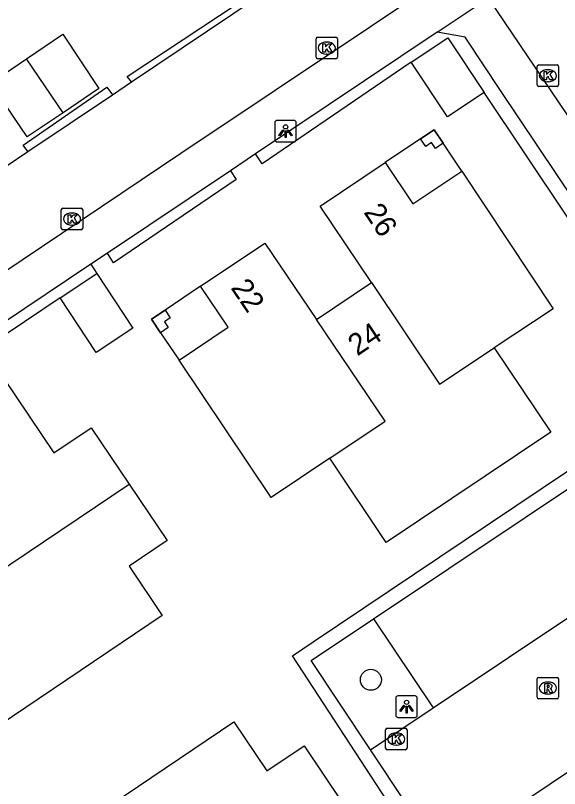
# Model space of a CAD drawing. Extents: x 158797 to 159887, y 384318 to 385255.
# Drawn here: x 158996.31 to 159021.65, y 384716.62 to 384752.65 of the extents above; entities that cross this region are included whole.
import ezdxf

# ---------------------------------------------------------------- set-up
doc = ezdxf.new("R2010")
doc.units = 0
for name, color, linetype in [('IMGEO_Boom', 7, 'Continuous'), ('IMGEO_Haag', 7, 'Continuous'), ('IMGEO_Kolk', 7, 'Continuous'), ('IMGEO_Lichtpunt', 7, 'Continuous'), ('IMGEO_Pand', 7, 'Continuous'), ('IMGEO_Pand_nummerreeks', 7, 'Continuous'), ('IMGEO_Pand_overbouw', 7, 'Continuous'), ('IMGEO_Parkeervlak_open', 7, 'Continuous'), ('IMGEO_Rijbaan_lokaal_open', 7, 'Continuous'), ('IMGEO_Rioolput', 7, 'Continuous'), ('IMGEO_Voetpad_open', 7, 'Continuous')]:
    doc.layers.add(name, color=color, linetype=linetype)

msp = doc.modelspace()

# ---------------------------------------------------------------- linework, layer by layer
at = {"layer": 'IMGEO_Boom'}
msp.add_circle((159012.861, 384721.691), 0.489, dxfattribs=at)
at = {"layer": 'IMGEO_Haag'}
for points in [[(159001.704, 384749.55), (159001.506, 384749.803), (159013.591, 384757.809), (159013.365, 384758.121)], [(159014.747, 384750.473), (159007.792, 384745.742), (159007.494, 384746.203)], [(158996.888, 384746.311), (158996.658, 384746.61), (159000.557, 384749.303), (159000.822, 384748.956)], [(159025.835, 384737.531), (159018.137, 384749.057)], [(159006.317, 384745.413), (159006.581, 384745.008), (159000.876, 384741.122), (159000.598, 384741.578)], [(158999.813, 384741.052), (159000.089, 384740.621)], [(158998.381, 384739.491), (158985.085, 384730.536)], [(159005.088, 384700.795), (159017.999, 384709.332), (159009.213, 384722.809), (159010.167, 384723.465), (159023.158, 384732.172), (159023.556, 384731.598)], [(159012.842, 384718.427), (159010.075, 384722.589), (159012.982, 384724.532)]]:
    msp.add_lwpolyline(points, dxfattribs=at)
at = {"layer": 'IMGEO_Kolk'}
for p, q in [((159010.383, 384751.632), (159011.235, 384751.632)), ((159010.308, 384750.706), (159010.308, 384751.558)), ((159010.796, 384751.412), (159010.821, 384751.412)), ((159011.309, 384751.558), (159011.309, 384750.706)), ((159011.235, 384750.632), (159010.383, 384750.632)), ((159010.819, 384750.852), (159010.794, 384750.852)), ((159020.607, 384749.417), (159020.607, 384750.269)), ((159020.682, 384750.343), (159021.534, 384750.343)), ((159021.608, 384750.269), (159021.608, 384749.417)), ((159021.095, 384750.123), (159021.12, 384750.123)), ((159021.118, 384749.563), (159021.093, 384749.563)), ((159021.534, 384749.343), (159020.682, 384749.343)), ((158998.441, 384742.738), (158998.441, 384743.59)), ((158998.516, 384743.664), (158999.368, 384743.664)), ((158998.929, 384743.444), (158998.954, 384743.444)), ((158999.442, 384743.59), (158999.442, 384742.738)), ((158999.368, 384742.664), (158998.516, 384742.664)), ((158998.952, 384742.884), (158998.927, 384742.884)), ((159013.547, 384718.503), (159013.547, 384719.355)), ((159013.622, 384719.429), (159014.474, 384719.429)), ((159014.035, 384719.209), (159014.06, 384719.209)), ((159014.548, 384719.355), (159014.548, 384718.503)), ((159014.058, 384718.649), (159014.033, 384718.649)), ((159014.474, 384718.429), (159013.622, 384718.429))]:
    msp.add_line(p, q, dxfattribs=at)
for points in [[(159010.383, 384751.632), (159011.235, 384751.632)], [(159010.308, 384750.706), (159010.308, 384751.558)], [(159010.629, 384751.332), (159010.752, 384751.332), (159010.752, 384751.181), (159010.882, 384751.332), (159011.046, 384751.332), (159010.9, 384751.181), (159011.053, 384750.932), (159010.901, 384750.932), (159010.816, 384751.096), (159010.752, 384751.029), (159010.752, 384750.932), (159010.629, 384750.932), (159010.629, 384751.332)], [(159011.309, 384751.558), (159011.309, 384750.706)], [(159011.235, 384750.632), (159010.383, 384750.632)], [(159020.607, 384749.417), (159020.607, 384750.269)], [(159020.682, 384750.343), (159021.534, 384750.343)], [(159021.608, 384750.269), (159021.608, 384749.417)], [(159020.928, 384750.043), (159021.051, 384750.043), (159021.051, 384749.892), (159021.181, 384750.043), (159021.345, 384750.043), (159021.199, 384749.892), (159021.352, 384749.643), (159021.2, 384749.643), (159021.115, 384749.807), (159021.051, 384749.74), (159021.051, 384749.643), (159020.928, 384749.643), (159020.928, 384750.043)], [(159021.534, 384749.343), (159020.682, 384749.343)], [(158998.441, 384742.738), (158998.441, 384743.59)], [(158998.516, 384743.664), (158999.368, 384743.664)], [(158998.762, 384743.364), (158998.885, 384743.364), (158998.885, 384743.213), (158999.015, 384743.364), (158999.179, 384743.364), (158999.033, 384743.213), (158999.186, 384742.964), (158999.034, 384742.964), (158998.949, 384743.128), (158998.885, 384743.061), (158998.885, 384742.964), (158998.762, 384742.964), (158998.762, 384743.364)], [(158999.442, 384743.59), (158999.442, 384742.738)], [(158999.368, 384742.664), (158998.516, 384742.664)], [(159013.547, 384718.503), (159013.547, 384719.355)], [(159013.622, 384719.429), (159014.474, 384719.429)], [(159014.548, 384719.355), (159014.548, 384718.503)], [(159013.868, 384719.129), (159013.991, 384719.129), (159013.991, 384718.978), (159014.121, 384719.129), (159014.285, 384719.129), (159014.139, 384718.978), (159014.292, 384718.729), (159014.14, 384718.729), (159014.055, 384718.893), (159013.991, 384718.826), (159013.991, 384718.729), (159013.868, 384718.729), (159013.868, 384719.129)], [(159014.474, 384718.429), (159013.622, 384718.429)]]:
    msp.add_lwpolyline(points, dxfattribs=at)
for centre, start, end in [((159010.385, 384751.556), 91.552, 178.448), ((159010.385, 384751.556), 91.552, 178.448), ((159011.233, 384751.556), 1.552, 88.448), ((159011.233, 384751.556), 1.552, 88.448), ((159010.385, 384750.708), 181.552, 268.448), ((159010.385, 384750.708), 181.552, 268.448), ((159011.233, 384750.708), 271.552, 358.448), ((159011.233, 384750.708), 271.552, 358.448), ((159020.684, 384750.267), 91.552, 178.448), ((159020.684, 384750.267), 91.552, 178.448), ((159021.532, 384750.267), 1.552, 88.448), ((159021.532, 384750.267), 1.552, 88.448), ((159020.684, 384749.419), 181.552, 268.448), ((159020.684, 384749.419), 181.552, 268.448), ((159021.532, 384749.419), 271.552, 358.448), ((159021.532, 384749.419), 271.552, 358.448), ((158998.518, 384743.588), 91.552, 178.448), ((158998.518, 384743.588), 91.552, 178.448), ((158999.366, 384743.588), 1.552, 88.448), ((158999.366, 384743.588), 1.552, 88.448), ((158998.518, 384742.74), 181.552, 268.448), ((158998.518, 384742.74), 181.552, 268.448), ((158999.366, 384742.74), 271.552, 358.448), ((158999.366, 384742.74), 271.552, 358.448), ((159013.624, 384719.353), 91.552, 178.448), ((159013.624, 384719.353), 91.552, 178.448), ((159014.472, 384719.353), 1.552, 88.448), ((159014.472, 384719.353), 1.552, 88.448), ((159013.624, 384718.505), 181.552, 268.448), ((159013.624, 384718.505), 181.552, 268.448), ((159014.472, 384718.505), 271.552, 358.448), ((159014.472, 384718.505), 271.552, 358.448)]:
    msp.add_arc(centre, 0.0765, start, end, dxfattribs=at)
for centre, major_axis, ratio, start_param, end_param in [((159010.795, 384751.132), (-0.387, 0.002), 0.722429, 4.712389, 7.853982), ((159010.82, 384751.132), (-0.39, 0.002), 0.717154, 1.570796, 4.712389), ((159021.094, 384749.843), (-0.387, 0.002), 0.722429, 4.712389, 7.853982), ((159021.119, 384749.843), (-0.39, 0.002), 0.717154, 1.570796, 4.712389), ((158998.928, 384743.164), (-0.387, 0.002), 0.722429, 4.712389, 7.853982), ((158998.953, 384743.164), (-0.39, 0.002), 0.717154, 1.570796, 4.712389), ((159014.034, 384718.929), (-0.387, 0.002), 0.722429, 4.712389, 7.853982), ((159014.059, 384718.929), (-0.39, 0.002), 0.717154, 1.570796, 4.712389)]:
    msp.add_ellipse(centre, major_axis=major_axis, ratio=ratio, start_param=start_param, end_param=end_param, dxfattribs=at)
at = {"layer": 'IMGEO_Lichtpunt'}
for p, q in [((159008.389, 384747.661), (159008.389, 384746.854)), ((159008.389, 384747.661), (159008.389, 384746.854)), ((159009.291, 384747.756), (159008.483, 384747.756)), ((159009.291, 384747.756), (159008.483, 384747.756)), ((159009.385, 384746.854), (159009.385, 384747.661)), ((159009.385, 384746.854), (159009.385, 384747.661)), ((159008.483, 384746.76), (159009.291, 384746.76)), ((159008.483, 384746.76), (159009.291, 384746.76)), ((159014.025, 384720.841), (159014.025, 384720.034)), ((159014.025, 384720.841), (159014.025, 384720.034)), ((159014.927, 384720.936), (159014.119, 384720.936)), ((159014.927, 384720.936), (159014.119, 384720.936)), ((159015.021, 384720.034), (159015.021, 384720.841)), ((159015.021, 384720.034), (159015.021, 384720.841)), ((159014.119, 384719.94), (159014.927, 384719.94)), ((159014.119, 384719.94), (159014.927, 384719.94))]:
    msp.add_line(p, q, dxfattribs=at)
for points in [[(159008.763, 384747.325), (159008.802, 384747.297), (159008.614, 384747.035), (159008.576, 384747.062), (159008.763, 384747.325)], [(159008.975, 384747.297), (159009.013, 384747.324), (159009.2, 384747.062), (159009.161, 384747.034), (159008.975, 384747.297)], [(159008.865, 384747.277), (159008.912, 384747.277), (159008.912, 384746.955), (159008.865, 384746.955), (159008.865, 384747.277)], [(159014.399, 384720.505), (159014.438, 384720.477), (159014.25, 384720.215), (159014.212, 384720.242), (159014.399, 384720.505)], [(159014.501, 384720.457), (159014.548, 384720.457), (159014.548, 384720.135), (159014.501, 384720.135), (159014.501, 384720.457)], [(159014.611, 384720.477), (159014.649, 384720.504), (159014.836, 384720.242), (159014.797, 384720.214), (159014.611, 384720.477)]]:
    msp.add_lwpolyline(points, dxfattribs=at)
for centre in [(159008.888, 384747.459), (159014.524, 384720.639)]:
    msp.add_circle(centre, 0.0994, dxfattribs=at)
for centre, start, end in [((159008.483, 384747.661), 90, 180), ((159008.483, 384747.661), 90, 180), ((159009.291, 384747.661), 0, 90), ((159009.291, 384747.661), 0, 90), ((159008.483, 384746.854), 180, 270), ((159008.483, 384746.854), 180, 270), ((159009.291, 384746.854), 270, 0), ((159009.291, 384746.854), 270, 360), ((159014.119, 384720.841), 90, 180), ((159014.119, 384720.841), 90, 180), ((159014.927, 384720.841), 0, 90), ((159014.927, 384720.841), 0, 90), ((159014.119, 384720.034), 180, 270), ((159014.119, 384720.034), 180, 270), ((159014.927, 384720.034), 270, 0), ((159014.927, 384720.034), 270, 360)]:
    msp.add_arc(centre, 0.0946, start, end, dxfattribs=at)
at = {"layer": 'IMGEO_Pand'}
for points in [[(158996.826, 384750.634), (158998.512, 384751.771), (159000.194, 384749.239), (158998.525, 384748.114)], [(159014.747, 384750.473), (159016.454, 384751.602), (159018.137, 384749.057)], [(158998.525, 384748.114), (158996.856, 384746.988), (158995.142, 384749.498), (158996.826, 384750.634)], [(158998.525, 384748.114), (158996.826, 384750.634)], [(159018.137, 384749.057), (159016.43, 384747.928), (159014.747, 384750.473)], [(159015.181, 384746.903), (159015.812, 384747.326), (159016.233, 384746.692), (159015.873, 384746.453), (159015.692, 384746.727), (159015.421, 384746.545), (159015.181, 384746.903)], [(159012.888, 384740.205), (159010.501, 384743.765), (159013.524, 384745.792), (159014.813, 384743.869), (159017.093, 384745.398), (159021.356, 384738.981), (159018.612, 384737.158)], [(159010.952, 384732.017), (159008.216, 384730.184), (159003.926, 384736.586), (159006.214, 384738.12), (159004.933, 384740.031), (159007.921, 384742.034), (159010.323, 384738.485)], [(159000.089, 384740.621), (159001.773, 384738.074), (159000.064, 384736.944), (158998.381, 384739.491)], [(158998.381, 384739.491), (159000.089, 384740.621)], [(159010.323, 384738.485), (159012.888, 384740.205)], [(159012.888, 384740.205), (159016.065, 384735.466), (159018.612, 384737.158)], [(159003.068, 384737.866), (159002.645, 384738.497), (159003.277, 384738.921), (159003.517, 384738.564), (159003.242, 384738.379), (159003.426, 384738.105), (159003.068, 384737.866)], [(159010.952, 384732.017), (159013.531, 384733.745), (159010.323, 384738.485)], [(159018.612, 384737.158), (159021.247, 384733.229), (159013.582, 384728.093), (159010.952, 384732.017)], [(158992.843, 384724.915), (158991.489, 384726.935), (158990.206, 384726.066), (158988.253, 384728.972), (158991.72, 384731.305), (158990.929, 384732.482), (158995.765, 384735.737), (158998.096, 384732.273), (158999.83, 384733.44), (159001.601, 384730.81)], [(159001.601, 384730.81), (159003.371, 384728.179), (159001.599, 384726.98), (159003.147, 384724.692), (158994.867, 384719.112), (158992.908, 384722.031), (158994.197, 384722.896), (158992.843, 384724.915)], [(158992.843, 384724.915), (159001.601, 384730.81)], [(159002.777, 384710.103), (159001.438, 384712.108), (159000.155, 384711.252), (158998.21, 384714.157), (159006.484, 384719.734), (159008.008, 384717.448), (159009.754, 384718.619), (159011.528, 384715.977)]]:
    msp.add_lwpolyline(points, dxfattribs=at)
at = {"layer": 'IMGEO_Pand_overbouw'}
for points in [[(159013.524, 384745.792), (159014.813, 384743.869), (159017.093, 384745.398), (159016.233, 384746.692), (159015.812, 384747.326), (159015.181, 384746.903)], [(159004.933, 384740.031), (159003.277, 384738.921), (159002.645, 384738.497), (159003.068, 384737.866), (159003.926, 384736.586), (159006.214, 384738.12)]]:
    msp.add_lwpolyline(points, close=True, dxfattribs=at)
at = {"layer": 'IMGEO_Parkeervlak_open'}
for points in [[(159012.982, 384724.532), (159023.556, 384731.598)], [(159012.982, 384724.532), (159015.764, 384720.383)]]:
    msp.add_lwpolyline(points, dxfattribs=at)
at = {"layer": 'IMGEO_Rijbaan_lokaal_open'}
for points in [[(159001.704, 384749.55), (159015.82, 384759.045), (159010.765, 384766.591)], [(159017.243, 384755.079), (159004.006, 384746.223), (158979.975, 384730.054), (158992.379, 384711.59), (159004.736, 384693.195)], [(159018.325, 384753.477), (159026.727, 384741.032), (159033.174, 384731.422)], [(159000.822, 384748.956), (159001.704, 384749.55)], [(158996.888, 384746.311), (159000.822, 384748.956)], [(158995.868, 384745.624), (158996.888, 384746.311)], [(159015.764, 384720.383), (159026.289, 384727.424)], [(159031.875, 384723.961), (159019.105, 384715.414)], [(159012.842, 384718.427), (159015.764, 384720.383)], [(159016.136, 384713.472), (159012.842, 384718.427)]]:
    msp.add_lwpolyline(points, dxfattribs=at)
at = {"layer": 'IMGEO_Rioolput'}
for p, q in [((159020.609, 384720.878), (159020.609, 384721.73)), ((159020.684, 384721.804), (159021.536, 384721.804)), ((159021.61, 384721.73), (159021.61, 384720.878)), ((159021.097, 384721.584), (159021.122, 384721.584)), ((159021.12, 384721.024), (159021.095, 384721.024)), ((159021.536, 384720.804), (159020.684, 384720.804))]:
    msp.add_line(p, q, dxfattribs=at)
for points in [[(159020.609, 384720.878), (159020.609, 384721.73)], [(159020.684, 384721.804), (159021.536, 384721.804)], [(159021.61, 384721.73), (159021.61, 384720.878)], [(159021.198, 384721.502), (159020.946, 384721.504), (159020.946, 384721.104)], [(159021.124, 384721.423), (159021.07, 384721.423), (159021.07, 384721.342)], [(159020.946, 384721.104), (159021.07, 384721.104), (159021.07, 384721.266), (159021.081, 384721.266)], [(159021.07, 384721.342), (159021.122, 384721.342)], [(159021.128, 384721.237), (159021.199, 384721.104), (159021.339, 384721.104), (159021.274, 384721.23)], [(159021.536, 384720.804), (159020.684, 384720.804)]]:
    msp.add_lwpolyline(points, dxfattribs=at)
for centre, radius, start, end in [((159020.686, 384721.728), 0.0765, 91.552, 178.448), ((159020.686, 384721.728), 0.0765, 91.552, 178.448), ((159021.534, 384721.728), 0.0765, 1.552, 88.448), ((159021.534, 384721.728), 0.0765, 1.552, 88.448), ((159021.13, 384721.327), 0.0964, 77.0061, 93.1865), ((159021.144, 384721.384), 0.0378, 276.6634, 79.6772), ((159021.197, 384721.392), 0.109, 350.3612, 89.416), ((159021.195, 384721.392), 0.112, 277.5842, 350.9817), ((159021.08, 384721.213), 0.0533, 26.0293, 88.6989), ((159021.106, 384721.531), 0.19, 274.7715, 282.9687), ((159021.179, 384721.177), 0.108, 29.5134, 73.7905), ((159020.686, 384720.88), 0.0765, 181.552, 268.448), ((159020.686, 384720.88), 0.0765, 181.552, 268.448), ((159021.534, 384720.88), 0.0765, 271.552, 358.448), ((159021.534, 384720.88), 0.0765, 271.552, 358.448)]:
    msp.add_arc(centre, radius, start, end, dxfattribs=at)
for centre, major_axis, ratio, start_param, end_param in [((159021.096, 384721.304), (-0.387, 0.002), 0.722429, 4.712389, 7.853982), ((159021.121, 384721.304), (-0.39, 0.002), 0.717154, 1.570796, 4.712389)]:
    msp.add_ellipse(centre, major_axis=major_axis, ratio=ratio, start_param=start_param, end_param=end_param, dxfattribs=at)
at = {"layer": 'IMGEO_Voetpad_open'}
for points in [[(159015.957, 384751.878), (159018.325, 384753.477)], [(159015.957, 384751.878), (159007.494, 384746.203)], [(159028.478, 384734.867), (159018.894, 384749.159), (159017.253, 384751.631), (159015.957, 384751.878)], [(159007.494, 384746.203), (159006.317, 384745.413)], [(159006.317, 384745.413), (159000.598, 384741.578)], [(159000.598, 384741.578), (158999.813, 384741.052)], [(158999.813, 384741.052), (158983.341, 384730.006), (158983.146, 384728.827), (158987.486, 384722.366)]]:
    msp.add_lwpolyline(points, dxfattribs=at)

# ---------------------------------------------------------------- texts
at = {"layer": 'IMGEO_Pand_nummerreeks'}
for s, rotation, p in [('26', 303.8444, (159012.502, 384743.476)), ('22', 304.0908, (159006.308, 384739.957)), ('24', 33.8446, (159012.229, 384736.754))]:
    msp.add_text(s, height=1, rotation=rotation, dxfattribs=at).set_placement(p)

doc.saveas('drawing.dxf')
